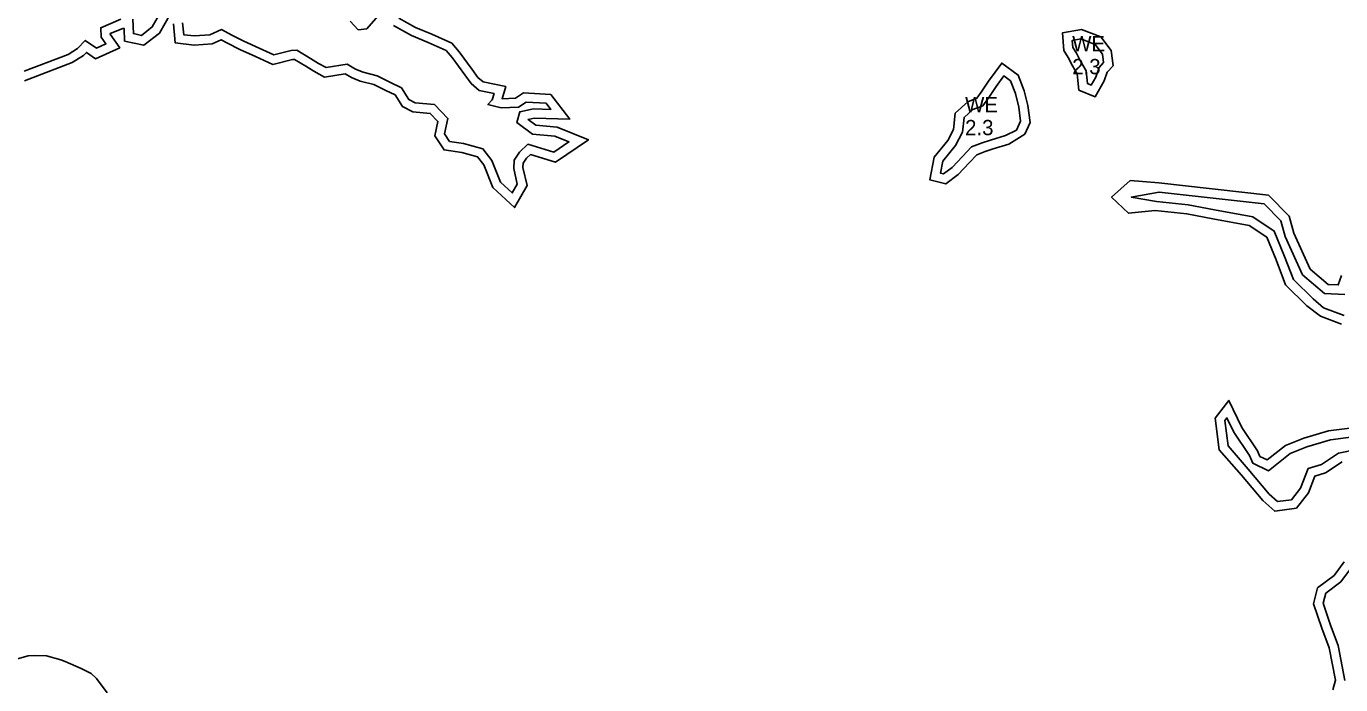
# Model space of a CAD drawing. Extents: x 2160437 to 2172832, y 205694 to 212444.
# Drawn here: x 2163349 to 2163779.2, y 210492.3 to 210707.8 of the extents above; entities that cross this region are included whole.
import ezdxf

# ---------------------------------------------------------------- set-up
doc = ezdxf.new("R2010")
doc.units = 0
for name, color, linetype in [('RD_EX_H2O', 7, 'Continuous'), ('RD_EX_H2O_Pond', 7, 'Continuous'), ('RD_EX_H2O_txCode', 7, 'Continuous'), ('RD_EX_VEG_ShrubLine', 7, 'Continuous'), ('RD_EX_VEG_TreeLine', 7, 'Continuous')]:
    doc.layers.add(name, color=color, linetype=linetype)

msp = doc.modelspace()

# ---------------------------------------------------------------- linework, layer by layer
at = {"layer": 'RD_EX_H2O'}
for points in [[(2163383.84, 210710.18), (2163384.06, 210705.41), (2163386.69, 210704.84), (2163390.24, 210707.58), (2163394.27, 210714.66)], [(2163348.28, 210693.1), (2163362.65, 210698.6), (2163365.79, 210700.56), (2163368.27, 210703.18), (2163371.92, 210700.6), (2163375.07, 210702.02), (2163373.54, 210704.25), (2163373.35, 210707.34), (2163379.97, 210710.1)], [(2163400.13, 210708.95), (2163400.51, 210705.06), (2163404.04, 210704.64), (2163409.07, 210705.04), (2163412.87, 210706.72), (2163416.26, 210704.91), (2163420.18, 210702.94), (2163425.21, 210700.64), (2163430, 210698.46), (2163435.65, 210699.85), (2163437.53, 210700.04), (2163442.05, 210697.25)], [(2163454.99, 210709.49), (2163457.61, 210706.59), (2163460.44, 210706.92), (2163464.12, 210711.21)], [(2163469.19, 210708.05), (2163475.11, 210704.75), (2163480.54, 210702.5), (2163486.37, 210699.87), (2163488.33, 210697.54), (2163492.5, 210691.9), (2163494.59, 210689.04), (2163497.18, 210686.78), (2163502.07, 210685.79), (2163501.44, 210683.75), (2163500.08, 210682.18), (2163504.41, 210681.09), (2163510.05, 210681.35), (2163512.56, 210683), (2163519.09, 210682.59), (2163520.63, 210680.56), (2163514.99, 210680.74), (2163510.47, 210679.82), (2163509.49, 210676.35), (2163514.62, 210672.53), (2163521.97, 210671.83), (2163526.6, 210669.98), (2163521.65, 210666.65), (2163513.18, 210669.18), (2163510.39, 210666.55), (2163508.71, 210664.02), (2163508.53, 210661.29), (2163509.69, 210656.16), (2163508.04, 210653.26), (2163504.18, 210656.83), (2163501.37, 210663.92), (2163498.44, 210667.74), (2163492.13, 210669.44), (2163487.5, 210670.12), (2163485.9, 210672.56), (2163487, 210677.64), (2163482.55, 210682.18), (2163476.3, 210682.7), (2163474.22, 210683.79), (2163471.78, 210687.63), (2163467.99, 210689.51), (2163463.78, 210691.58), (2163459.2, 210692.74), (2163456.73, 210693.76), (2163454.02, 210695.39), (2163447.11, 210694.32), (2163444.59, 210695.67), (2163442.05, 210697.25)], [(2163780.28, 210613.18), (2163773.58, 210615.69), (2163770.12, 210618.56), (2163763.69, 210624.89), (2163760.79, 210632.42), (2163757.4, 210640.79), (2163750.37, 210645.41), (2163737.89, 210647.71), (2163729.21, 210649.35), (2163718.89, 210650.46), (2163710.62, 210651.92), (2163719.72, 210653.56), (2163754.15, 210649.66), (2163759.57, 210644.09), (2163760.97, 210639.05), (2163766.68, 210626.48), (2163773.84, 210620.38), (2163780.48, 210620.04)], [(2163784.31, 210569.23), (2163778.42, 210568.06), (2163772.9, 210564.35), (2163768.47, 210563.08), (2163765.99, 210556.6), (2163763.06, 210552.84), (2163758.53, 210552.25), (2163755.8, 210554.64), (2163748.93, 210562.82), (2163742.28, 210570.43), (2163741.22, 210578.72), (2163741.95, 210579.66), (2163744.14, 210574.98), (2163749.27, 210567.33), (2163750.43, 210564.77), (2163755.51, 210562.35), (2163762.59, 210567.98), (2163768.11, 210570.1), (2163775.79, 210572.46), (2163787.42, 210573.93)], [(2163780.48, 210493.71), (2163778.31, 210505.18), (2163775.87, 210511.78), (2163773.44, 210518.94), (2163774.26, 210522.21), (2163779.16, 210525.96), (2163782.66, 210530.64)]]:
    msp.add_lwpolyline(points, dxfattribs=at)
at = {"layer": 'RD_EX_H2O_Pond'}
for points in [[(2163692.68, 210698.96), (2163691.51, 210700.86), (2163691.33, 210703.2), (2163694.06, 210703.68), (2163698.79, 210701.86), (2163701.16, 210698.67), (2163701.55, 210695.9), (2163700.1, 210694.33), (2163698.98, 210691.19), (2163697.49, 210688.54), (2163696.29, 210689.03), (2163695.87, 210693.24), (2163694.01, 210696.36)], [(2163673.02, 210673.77), (2163669.48, 210672.03), (2163664.59, 210670.53), (2163661.8, 210669.67), (2163658.32, 210668.33), (2163655.37, 210665.14), (2163651.96, 210661.56), (2163649.22, 210659.47), (2163648.19, 210659.72), (2163648.91, 210663.67), (2163653.07, 210668.77), (2163655.36, 210673.12), (2163655.88, 210677.95), (2163658.76, 210680.53), (2163662.02, 210681.81), (2163663.98, 210684.54), (2163666.36, 210688.14), (2163668.87, 210691.56), (2163671.14, 210689.93), (2163672.71, 210685.8), (2163673.77, 210681.34), (2163674.4, 210676.79)]]:
    msp.add_lwpolyline(points, close=True, dxfattribs=at)
at = {"layer": 'RD_EX_VEG_ShrubLine'}
for points in [[(2163348.4, 210689.93), (2163363.99, 210695.9), (2163367.7, 210698.22), (2163368.66, 210699.23), (2163371.59, 210697.16), (2163379.56, 210700.76), (2163376.48, 210705.26), (2163376.48, 210705.39), (2163380.6, 210707.11), (2163380.98, 210707.12), (2163381.17, 210702.96), (2163387.42, 210701.61), (2163392.54, 210705.57), (2163396.26, 210712.08)], [(2163397.15, 210708.58), (2163397.75, 210702.37), (2163403.98, 210701.62), (2163409.81, 210702.09), (2163412.74, 210703.39), (2163414.88, 210702.25), (2163418.88, 210700.23), (2163423.97, 210697.91), (2163429.71, 210695.3), (2163436.16, 210696.89), (2163436.82, 210696.95), (2163440.48, 210694.7)], [(2163440.48, 210694.7), (2163443.08, 210693.07), (2163446.58, 210691.2), (2163453.4, 210692.26), (2163455.38, 210691.07), (2163458.25, 210689.89), (2163462.74, 210688.75), (2163466.67, 210686.82), (2163469.69, 210685.32), (2163472.12, 210681.5), (2163475.45, 210679.76), (2163481.19, 210679.28), (2163483.73, 210676.69), (2163482.7, 210671.98), (2163485.72, 210667.34), (2163491.52, 210666.5), (2163496.68, 210665.11), (2163498.73, 210662.43), (2163501.64, 210655.09), (2163508.79, 210648.49), (2163512.87, 210655.69), (2163511.55, 210661.53), (2163511.65, 210663.02), (2163512.7, 210664.6), (2163513.98, 210665.81), (2163522.14, 210663.37), (2163532.98, 210670.65), (2163522.69, 210674.78), (2163515.74, 210675.44), (2163513.21, 210677.31), (2163515.24, 210677.73), (2163526.84, 210677.36), (2163520.64, 210685.5), (2163511.75, 210686.05), (2163509.09, 210684.31), (2163504.71, 210684.1), (2163504.69, 210684.11), (2163505.92, 210688.08), (2163498.55, 210689.57), (2163496.81, 210691.08), (2163494.92, 210693.67), (2163490.69, 210699.4), (2163488.22, 210702.33), (2163481.74, 210705.25), (2163476.42, 210707.45), (2163470.93, 210710.51)], [(2163779.4, 210626.24), (2163778.37, 210623.16), (2163775.01, 210623.33), (2163769.14, 210628.33), (2163763.79, 210640.07), (2163762.26, 210645.63), (2163755.55, 210652.52), (2163719.62, 210656.59), (2163710.29, 210657.29), (2163704.19, 210651.92), (2163709.7, 210646.63), (2163718.47, 210647.49), (2163728.78, 210646.38), (2163737.34, 210644.76), (2163749.23, 210642.57), (2163754.97, 210638.8), (2163758, 210631.31), (2163761.12, 210623.21), (2163768.1, 210616.34), (2163772.53, 210612.88), (2163772.53, 210612.88), (2163779.38, 210610.32)], [(2163787.38, 210576.95), (2163775.16, 210575.4), (2163767.13, 210572.94), (2163761.08, 210570.61), (2163755.11, 210565.86), (2163752.71, 210567), (2163751.91, 210568.79), (2163746.76, 210576.46), (2163742.6, 210585.36), (2163738.09, 210579.58), (2163739.42, 210569.15), (2163746.65, 210560.87), (2163753.65, 210552.54), (2163757.57, 210549.09), (2163764.67, 210550.03), (2163768.63, 210555.1), (2163770.73, 210560.6), (2163774.18, 210561.59), (2163779.59, 210565.23)], [(2163780.27, 210532.46), (2163777, 210528.09), (2163771.6, 210523.96), (2163770.31, 210518.81), (2163773.04, 210510.78), (2163775.4, 210504.37), (2163777.41, 210493.8), (2163776.62, 210490.63)]]:
    msp.add_lwpolyline(points, dxfattribs=at)
for points in [[(2163690.01, 210697.6), (2163691.39, 210694.91), (2163692.95, 210692.28), (2163693.48, 210686.94), (2163698.81, 210684.75), (2163701.73, 210689.94), (2163702.72, 210692.74), (2163704.71, 210694.91), (2163704.03, 210699.85), (2163700.67, 210704.35), (2163694.37, 210706.78), (2163688.12, 210705.68), (2163688.58, 210699.9)], [(2163675.75, 210672.53), (2163677.49, 210676.34), (2163676.72, 210681.89), (2163675.58, 210686.68), (2163673.63, 210691.83), (2163668.21, 210695.74), (2163663.9, 210689.85), (2163661.51, 210686.24), (2163660.1, 210684.28), (2163657.16, 210683.13), (2163653.02, 210679.41), (2163652.44, 210674.01), (2163650.55, 210670.43), (2163646.1, 210664.97), (2163644.73, 210657.5), (2163649.89, 210656.2), (2163653.97, 210659.32), (2163657.56, 210663.09), (2163660.05, 210665.78), (2163662.78, 210666.83), (2163665.47, 210667.66), (2163670.59, 210669.23)]]:
    msp.add_lwpolyline(points, close=True, dxfattribs=at)
at = {"layer": 'RD_EX_VEG_TreeLine'}
msp.add_lwpolyline([(2163338.13, 210492.12), (2163338.87, 210494.31), (2163340.44, 210496.79), (2163343.11, 210499.56), (2163344.54, 210500.37), (2163349.63, 210501.71), (2163351.69, 210501.87), (2163355.59, 210501.76), (2163360.34, 210500.44), (2163361.66, 210499.91), (2163366.99, 210497.61), (2163370.21, 210495.94), (2163371.93, 210494.28), (2163375.5, 210489.64)], dxfattribs=at)

# ---------------------------------------------------------------- texts
at = {"layer": 'RD_EX_H2O_txCode'}
for s, p in [('WE', (2163691.28, 210699.61)), ('2.3', (2163691.28, 210692.11)), ('WE', (2163656.23, 210679.66)), ('2.3', (2163656.23, 210672.16))]:
    msp.add_text(s, height=5, dxfattribs=at).set_placement(p)

doc.saveas('drawing.dxf')
